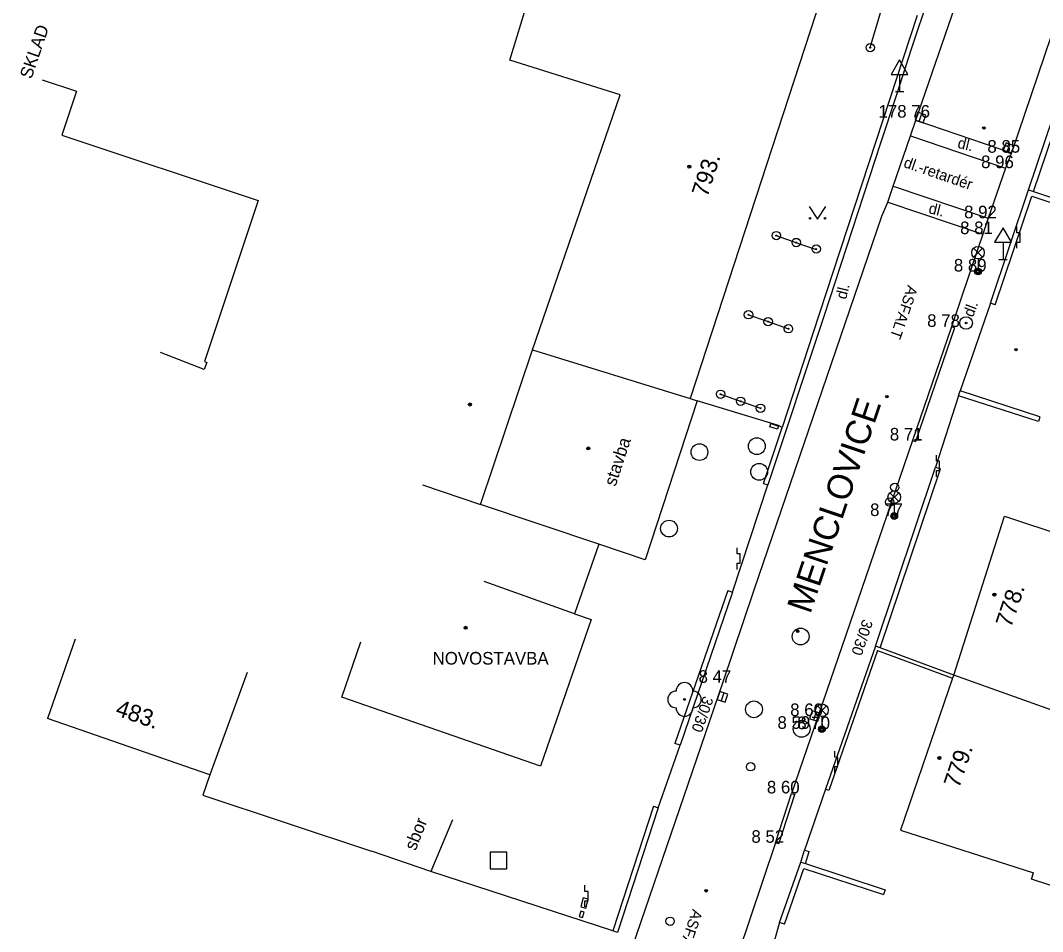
# Model space of a CAD drawing. Extents: x -538441 to -536770, y -1181008 to -1179809.
# Drawn here: x -538153.7 to -538092.8, y -1180711.7 to -1180657.4 of the extents above; entities that cross this region are included whole.
import ezdxf

# ---------------------------------------------------------------- set-up
doc = ezdxf.new("R2010")
doc.units = 0
for name, color, linetype in [('Vrstva 10', 7, 'Continuous'), ('Vrstva 11', 7, 'Continuous'), ('Vrstva 20', 7, 'Continuous'), ('Vrstva 21', 7, 'Continuous'), ('Vrstva 22', 7, 'Continuous'), ('Vrstva 24', 7, 'Continuous'), ('Vrstva 25', 7, 'Continuous'), ('Vrstva 26', 7, 'Continuous'), ('Vrstva 27', 7, 'Continuous'), ('Vrstva 28', 7, 'Continuous'), ('Vrstva 33', 7, 'Continuous'), ('Vrstva 34', 7, 'Continuous'), ('Vrstva 36', 7, 'Continuous'), ('Vrstva 39', 7, 'Continuous'), ('Vrstva 4', 7, 'Continuous'), ('Vrstva 40', 7, 'Continuous'), ('Vrstva 41', 7, 'Continuous'), ('Vrstva 47', 7, 'Continuous'), ('Vrstva 49', 7, 'Continuous'), ('Vrstva 5', 7, 'Continuous'), ('Vrstva 7', 7, 'Continuous'), ('Vrstva 8', 7, 'Continuous')]:
    doc.layers.add(name, color=color, linetype=linetype)

msp = doc.modelspace()

# ---------------------------------------------------------------- linework, layer by layer
at = {"layer": 'Vrstva 10'}
for p, q in [((-538090.51, -1180652.96), (-538094.67, -1180665.24)), ((-538100.376, -1180663.311), (-538097.28, -1180654.29)), ((-538103.09, -1180658.98), (-538102.38, -1180656.57)), ((-538094.67, -1180665.24), (-538095.03, -1180666.16)), ((-538095.03, -1180666.16), (-538096.06, -1180669.15)), ((-538096.67, -1180670.9), (-538098.26, -1180675.62)), ((-538098.26, -1180675.62), (-538100.58, -1180682.39)), ((-538108.73, -1180706.36), (-538107.78, -1180703.42)), ((-538108.73, -1180706.36), (-538112.31, -1180716.94))]:
    msp.add_line(p, q, dxfattribs=at)
for points in [[(-538102.4, -1180669.03), (-538102.046, -1180668.178), (-538101.723, -1180667.235), (-538100.696, -1180664.244), (-538100.376, -1180663.311)], [(-538111.88, -1180696.83), (-538110, -1180691.28), (-538102.4, -1180669.03)], [(-538096.06, -1180669.15), (-538096.39, -1180670.09), (-538096.67, -1180670.9)], [(-538108.688, -1180670.176), (-538107.529, -1180670.593), (-538106.31, -1180671.01)], [(-538110.344, -1180674.894), (-538109.174, -1180675.307), (-538107.966, -1180675.728)], [(-538112.008, -1180679.636), (-538110.819, -1180680.053), (-538109.63, -1180680.47)], [(-538100.58, -1180682.39), (-538103.86, -1180691.97), (-538107.78, -1180703.42)], [(-538126.17, -1180738.76), (-538120.85, -1180723.06), (-538111.88, -1180696.83)]]:
    msp.add_lwpolyline(points, dxfattribs=at)
at = {"layer": 'Vrstva 11'}
for p, q in [((-538100.376, -1180663.311), (-538094.67, -1180665.24)), ((-538100.696, -1180664.244), (-538095.03, -1180666.16)), ((-538101.723, -1180667.235), (-538096.06, -1180669.15)), ((-538102.046, -1180668.178), (-538096.39, -1180670.09)), ((-538098.07, -1180675.684), (-538100.39, -1180682.454)), ((-538098.07, -1180675.684), (-538098.26, -1180675.62)), ((-538100.58, -1180682.39), (-538100.39, -1180682.454)), ((-538108.539, -1180706.421), (-538107.589, -1180703.481)), ((-538107.78, -1180703.42), (-538107.589, -1180703.481)), ((-538108.539, -1180706.421), (-538108.73, -1180706.36))]:
    msp.add_line(p, q, dxfattribs=at)
at = {"layer": 'Vrstva 20'}
for centre, radius in [((-538096.32, -1180663.77), 0.075), ((-538096.32, -1180663.77), 0.0204), ((-538094.41, -1180676.98), 0.075), ((-538094.41, -1180676.98), 0.0204), ((-538102.1, -1180679.78), 0.075), ((-538102.1, -1180679.78), 0.0204), ((-538107.42, -1180693.748), 0.075), ((-538107.42, -1180693.748), 0.0204), ((-538112.87, -1180709.22), 0.075), ((-538112.87, -1180709.22), 0.0204)]:
    msp.add_circle(centre, radius, dxfattribs=at)
at = {"layer": 'Vrstva 21'}
for radius in [0.375, 0.05]:
    msp.add_circle((-538097.38, -1180675.39), radius, dxfattribs=at)
at = {"layer": 'Vrstva 22'}
msp.add_circle((-538114.16, -1180697.82), 0.05, dxfattribs=at)
for centre, start, end in [((-538114.16, -1180697.32), 0, 180), ((-538114.66, -1180697.82), 90, 270), ((-538113.66, -1180697.82), 270, 90), ((-538114.16, -1180698.32), 180, 0)]:
    msp.add_arc(centre, 0.5, start, end, dxfattribs=at)
at = {"layer": 'Vrstva 24'}
for p, q in [((-538094.349, -1180670.009), (-538094.35, -1180669.641)), ((-538094.166, -1180670.01), (-538094.349, -1180670.009)), ((-538094.166, -1180670.562), (-538094.166, -1180670.01)), ((-538094.35, -1180670.93), (-538094.349, -1180670.562)), ((-538094.349, -1180670.562), (-538094.166, -1180670.562)), ((-538099.139, -1180683.629), (-538099.14, -1180683.261)), ((-538098.956, -1180683.63), (-538099.139, -1180683.629)), ((-538098.956, -1180684.182), (-538098.956, -1180683.63)), ((-538099.14, -1180684.55), (-538099.139, -1180684.182)), ((-538099.139, -1180684.182), (-538098.956, -1180684.182)), ((-538111.019, -1180689.149), (-538111.02, -1180688.781)), ((-538110.836, -1180689.15), (-538111.019, -1180689.149)), ((-538110.836, -1180689.702), (-538110.836, -1180689.15)), ((-538111.02, -1180690.07), (-538111.019, -1180689.702)), ((-538111.019, -1180689.702), (-538110.836, -1180689.702)), ((-538105.209, -1180701.269), (-538105.21, -1180700.901)), ((-538105.026, -1180701.27), (-538105.209, -1180701.269)), ((-538105.026, -1180701.822), (-538105.026, -1180701.27)), ((-538105.21, -1180702.19), (-538105.209, -1180701.822)), ((-538105.209, -1180701.822), (-538105.026, -1180701.822)), ((-538120.09, -1180709.259), (-538120.09, -1180708.891)), ((-538119.907, -1180709.261), (-538120.09, -1180709.259)), ((-538119.907, -1180709.813), (-538119.907, -1180709.261)), ((-538120.09, -1180710.18), (-538120.09, -1180709.813)), ((-538120.09, -1180709.813), (-538119.907, -1180709.813))]:
    msp.add_line(p, q, dxfattribs=at)
for points in [[(-538109.07, -1180681.57), (-538109.007, -1180681.38), (-538108.561, -1180681.527), (-538108.623, -1180681.717), (-538109.07, -1180681.57)], [(-538120.19, -1180709.651), (-538120.33, -1180710.181), (-538120.03, -1180710.26), (-538119.89, -1180709.73), (-538120.19, -1180709.651)], [(-538120.425, -1180710.759), (-538120.23, -1180710.82), (-538120.13, -1180710.5), (-538120.332, -1180710.437), (-538120.425, -1180710.759)]]:
    msp.add_lwpolyline(points, dxfattribs=at)
at = {"layer": 'Vrstva 25'}
for centre, radius in [((-538103.09, -1180658.98), 0.25), ((-538103.09, -1180658.98), 0.0303), ((-538108.688, -1180670.176), 0.25), ((-538108.688, -1180670.176), 0.0303), ((-538107.499, -1180670.593), 0.25), ((-538107.499, -1180670.593), 0.0303), ((-538106.31, -1180670.98), 0.25), ((-538106.31, -1180670.98), 0.0303), ((-538110.344, -1180674.894), 0.25), ((-538110.344, -1180674.894), 0.0303), ((-538109.174, -1180675.307), 0.25), ((-538109.174, -1180675.307), 0.0303), ((-538107.966, -1180675.728), 0.25), ((-538107.966, -1180675.728), 0.0303), ((-538112.008, -1180679.636), 0.25), ((-538112.008, -1180679.636), 0.0303), ((-538110.819, -1180680.053), 0.25), ((-538110.819, -1180680.053), 0.0303), ((-538109.63, -1180680.47), 0.25), ((-538109.63, -1180680.47), 0.0303)]:
    msp.add_circle(centre, radius, dxfattribs=at)
at = {"layer": 'Vrstva 26'}
msp.add_lwpolyline([(-538125.739, -1180707.919), (-538124.741, -1180707.919), (-538124.741, -1180706.919), (-538125.739, -1180706.919)], close=True, dxfattribs=at)
at = {"layer": 'Vrstva 27'}
for p, q in [((-538100.183, -1180663.386), (-538100.017, -1180662.914)), ((-538094.945, -1180665.201), (-538094.755, -1180664.739)), ((-538111.819, -1180697.433), (-538111.981, -1180697.907)), ((-538106.461, -1180699.05), (-538106.319, -1180698.57))]:
    msp.add_line(p, q, dxfattribs=at)
for points in [[(-538099.947, -1180663.469), (-538099.781, -1180662.997), (-538100.253, -1180662.831), (-538100.419, -1180663.303)], [(-538094.714, -1180665.297), (-538094.523, -1180664.834), (-538094.986, -1180664.643), (-538095.177, -1180665.106)], [(-538112.056, -1180697.353), (-538112.217, -1180697.826), (-538111.744, -1180697.987), (-538111.583, -1180697.514)], [(-538106.222, -1180699.121), (-538106.079, -1180698.642), (-538106.558, -1180698.499), (-538106.701, -1180698.978)]]:
    msp.add_lwpolyline(points, close=True, dxfattribs=at)
for centre in [(-538113.27, -1180683.08), (-538109.85, -1180682.73), (-538109.71, -1180684.26), (-538115.08, -1180687.64), (-538107.24, -1180694.07), (-538110.02, -1180698.41), (-538107.18, -1180699.57)]:
    msp.add_circle(centre, 0.5, dxfattribs=at)
at = {"layer": 'Vrstva 28'}
for centre in [(-538101.63, -1180685.18), (-538101.94, -1180686.06), (-538110.22, -1180701.83), (-538115.02, -1180711.04)]:
    msp.add_circle(centre, 0.25, dxfattribs=at)
at = {"layer": 'Vrstva 33'}
for p, q in [((-538096.935, -1180671.46), (-538096.405, -1180670.93)), ((-538096.935, -1180670.93), (-538096.405, -1180671.46)), ((-538096.67, -1180671.57), (-538096.67, -1180672.32)), ((-538101.925, -1180686.03), (-538101.395, -1180685.5)), ((-538101.925, -1180685.5), (-538101.395, -1180686.03)), ((-538101.66, -1180686.14), (-538101.66, -1180686.89)), ((-538106.235, -1180698.73), (-538105.705, -1180698.2)), ((-538106.235, -1180698.2), (-538105.705, -1180698.73)), ((-538105.97, -1180698.84), (-538105.97, -1180699.59))]:
    msp.add_line(p, q, dxfattribs=at)
for centre, radius in [((-538096.67, -1180671.195), 0.375), ((-538096.67, -1180672.32), 0.2), ((-538096.67, -1180672.32), 0.145), ((-538096.67, -1180672.32), 0.0876), ((-538101.66, -1180685.765), 0.375), ((-538101.66, -1180686.89), 0.2), ((-538101.66, -1180686.89), 0.145), ((-538101.66, -1180686.89), 0.0876), ((-538105.97, -1180698.465), 0.375), ((-538105.97, -1180699.59), 0.2), ((-538105.97, -1180699.59), 0.145), ((-538105.97, -1180699.59), 0.0876)]:
    msp.add_circle(centre, radius, dxfattribs=at)
at = {"layer": 'Vrstva 34'}
for p, q in [((-538101.345, -1180660.576), (-538101.345, -1180661.594)), ((-538101.595, -1180661.594), (-538101.095, -1180661.594)), ((-538095.18, -1180670.58), (-538095.18, -1180671.598)), ((-538095.43, -1180671.598), (-538094.93, -1180671.598))]:
    msp.add_line(p, q, dxfattribs=at)
for points in [[(-538101.845, -1180660.576), (-538100.845, -1180660.576), (-538101.345, -1180659.71)], [(-538095.68, -1180670.58), (-538094.68, -1180670.58), (-538095.18, -1180669.714)]]:
    msp.add_lwpolyline(points, close=True, dxfattribs=at)
at = {"layer": 'Vrstva 36'}
msp.add_lwpolyline([(-538106.734, -1180668.448), (-538106.234, -1180669.198), (-538105.734, -1180668.448)], dxfattribs=at)
for centre in [(-538106.684, -1180669.148), (-538105.785, -1180669.148)]:
    msp.add_circle(centre, 0.05, dxfattribs=at)
at = {"layer": 'Vrstva 39'}
for centre, radius in [((-538113.871, -1180666.069), 0.09), ((-538113.871, -1180666.069), 0.0398), ((-538126.942, -1180680.244), 0.09), ((-538126.942, -1180680.244), 0.0398), ((-538119.889, -1180682.864), 0.09), ((-538119.889, -1180682.864), 0.0398), ((-538095.698, -1180691.573), 0.09), ((-538095.698, -1180691.573), 0.0398), ((-538127.204, -1180693.548), 0.09), ((-538127.204, -1180693.548), 0.0398), ((-538098.973, -1180701.309), 0.09), ((-538098.973, -1180701.309), 0.0398)]:
    msp.add_circle(centre, radius, dxfattribs=at)
at = {"layer": 'Vrstva 5'}
for p, q in [((-538105.78, -1180655.28), (-538113.83, -1180679.89)), ((-538117.99, -1180661.8), (-538124.57, -1180659.73)), ((-538152.431, -1180660.9), (-538150.39, -1180661.58)), ((-538150.39, -1180661.58), (-538151.26, -1180664.19)), ((-538123.21, -1180676.99), (-538117.99, -1180661.8)), ((-538151.26, -1180664.19), (-538139.554, -1180668.092)), ((-538139.554, -1180668.092), (-538142.75, -1180677.68)), ((-538126.31, -1180686.2), (-538123.21, -1180676.99)), ((-538123.21, -1180676.99), (-538113.83, -1180679.89)), ((-538142.78, -1180678.15), (-538145.368, -1180677.14)), ((-538142.75, -1180677.68), (-538142.62, -1180677.74)), ((-538142.62, -1180677.74), (-538142.78, -1180678.15)), ((-538113.402, -1180680.03), (-538116.5, -1180689.5)), ((-538113.83, -1180679.89), (-538113.402, -1180680.03)), ((-538129.762, -1180685.038), (-538126.31, -1180686.2)), ((-538098.12, -1180696.37), (-538095.09, -1180686.89)), ((-538095.09, -1180686.89), (-538087.19, -1180689.55)), ((-538119.267, -1180688.569), (-538120.706, -1180692.719)), ((-538120.706, -1180692.719), (-538126.103, -1180690.798)), ((-538120.706, -1180692.719), (-538119.72, -1180693.06)), ((-538119.72, -1180693.06), (-538122.74, -1180701.79)), ((-538150.47, -1180694.226), (-538152.11, -1180698.95)), ((-538134.58, -1180697.68), (-538133.436, -1180694.385)), ((-538140.21, -1180696.21), (-538142.43, -1180702.31)), ((-538090.48, -1180699.11), (-538098.12, -1180696.37)), ((-538122.74, -1180701.79), (-538134.58, -1180697.68)), ((-538142.43, -1180702.31), (-538152.11, -1180698.95)), ((-538127.98, -1180704.99), (-538129.27, -1180708.07)), ((-538101.28, -1180705.6), (-538093.36, -1180708.16)), ((-538129.27, -1180708.07), (-538132.81, -1180706.86)), ((-538093.48, -1180708.52), (-538093.36, -1180708.16)), ((-538091.48, -1180709.18), (-538093.48, -1180708.52))]:
    msp.add_line(p, q, dxfattribs=at)
for points in [[(-538124.57, -1180659.73), (-538123.683, -1180656.862), (-538121.816, -1180650.822)], [(-538116.5, -1180689.5), (-538119.267, -1180688.569), (-538126.31, -1180686.2)], [(-538098.12, -1180696.37), (-538098.185, -1180696.559), (-538101.28, -1180705.6)]]:
    msp.add_lwpolyline(points, dxfattribs=at)
at = {"layer": 'Vrstva 7'}
for p, q in [((-538098.766, -1180653.367), (-538100.625, -1180659.018)), ((-538100.302, -1180657.074), (-538102.765, -1180664.577)), ((-538093.375, -1180667.554), (-538090.52, -1180659.12)), ((-538102.765, -1180664.577), (-538106.145, -1180674.917)), ((-538102.48, -1180664.67), (-538105.86, -1180675.01)), ((-538095.646, -1180674.296), (-538093.471, -1180667.839)), ((-538093.471, -1180667.839), (-538088.913, -1180669.352)), ((-538105.86, -1180675.01), (-538109.19, -1180685.04)), ((-538106.145, -1180674.917), (-538108.333, -1180681.611)), ((-538092.98, -1180680.971), (-538097.74, -1180679.44)), ((-538102.498, -1180694.745), (-538098.915, -1180684.075)), ((-538109.443, -1180684.956), (-538109.19, -1180685.04)), ((-538111.584, -1180691.331), (-538114.742, -1180700.439)), ((-538102.78, -1180694.64), (-538105.75, -1180703.17)), ((-538102.658, -1180694.899), (-538098.185, -1180696.559)), ((-538142.43, -1180702.31), (-538142.85, -1180703.52)), ((-538142.85, -1180703.52), (-538132.81, -1180706.86)), ((-538116.015, -1180704.177), (-538118.435, -1180711.617)), ((-538106.944, -1180707.604), (-538106.723, -1180706.889)), ((-538118.435, -1180711.617), (-538129.27, -1180708.07))]:
    msp.add_line(p, q, dxfattribs=at)
for points in [[(-538093.66, -1180667.46), (-538090.71, -1180658.7), (-538090.426, -1180658.796)], [(-538100.625, -1180659.018), (-538101.554, -1180661.844), (-538102.48, -1180664.67)], [(-538095.646, -1180674.296), (-538095.93, -1180674.2), (-538093.66, -1180667.46)], [(-538093.66, -1180667.46), (-538093.375, -1180667.554), (-538088.81, -1180669.07)], [(-538092.98, -1180680.971), (-538093.071, -1180681.256), (-538097.831, -1180679.725), (-538097.74, -1180679.44)], [(-538108.56, -1180681.49), (-538113.402, -1180680.03)], [(-538109.443, -1180684.956), (-538108.333, -1180681.611), (-538108.56, -1180681.49)], [(-538102.78, -1180694.64), (-538099.2, -1180683.98), (-538098.915, -1180684.075)], [(-538111.584, -1180691.331), (-538111.3, -1180691.43), (-538114.42, -1180700.55)], [(-538098.12, -1180696.37), (-538102.498, -1180694.745), (-538102.78, -1180694.64)], [(-538102.658, -1180694.899), (-538105.561, -1180703.236), (-538105.75, -1180703.17)], [(-538114.42, -1180700.55), (-538114.742, -1180700.439)], [(-538116.015, -1180704.177), (-538115.73, -1180704.27), (-538118.15, -1180711.71), (-538118.435, -1180711.617)], [(-538107.23, -1180707.51), (-538107.01, -1180706.8), (-538106.723, -1180706.889)], [(-538108.207, -1180711.209), (-538108.49, -1180711.11), (-538107.23, -1180707.51)], [(-538107.23, -1180707.51), (-538106.944, -1180707.604), (-538102.2, -1180709.16), (-538102.294, -1180709.445)], [(-538108.207, -1180711.209), (-538107.044, -1180707.887), (-538102.294, -1180709.445)]]:
    msp.add_lwpolyline(points, dxfattribs=at)
at = {"layer": 'Vrstva 8'}
for p, q in [((-538095.93, -1180674.2), (-538097.74, -1180679.44)), ((-538097.831, -1180679.725), (-538099.2, -1180683.98)), ((-538111.3, -1180691.43), (-538109.19, -1180685.04)), ((-538115.73, -1180704.27), (-538114.42, -1180700.55)), ((-538105.75, -1180703.17), (-538107.01, -1180706.8)), ((-538108.49, -1180711.11), (-538108.79, -1180712.16))]:
    msp.add_line(p, q, dxfattribs=at)

# ---------------------------------------------------------------- texts
at = {"layer": 'Vrstva 4'}
for s, p in [('178 76 ', (-538102.6, -1180663.15)), (' 8 85', (-538096.39, -1180665.24)), (' 8 96', (-538096.766, -1180666.16)), (' 8 92', (-538097.779, -1180669.15)), (' 8 81', (-538098.015, -1180670.09)), (' 8 89', (-538098.389, -1180672.32)), (' 8 78', (-538099.979, -1180675.62)), (' 8 71', (-538102.205, -1180682.39)), (' 8 77', (-538103.379, -1180686.89)), (' 8 47', (-538113.599, -1180696.83)), (' 8 60', (-538108.139, -1180698.81)), (' 8 59', (-538108.899, -1180699.57)), (' 8 70', (-538107.719, -1180699.59)), (' 8 60', (-538109.529, -1180703.42)), (' 8 52', (-538110.449, -1180706.36))]:
    msp.add_text(s, height=0.75, dxfattribs=at).set_placement(p)
at = {"layer": 'Vrstva 40'}
for s, rotation, p in [('dl.', 346.25013, (-538097.932, -1180664.944)), ('dl.-retardér', 341.03671, (-538101.152, -1180666.085)), ('dl.', 346.25013, (-538099.658, -1180668.838)), ('dl.', 76.25012, (-538104.529, -1180674.012)), ('ASFALT', 251.00783, (-538100.857, -1180673.095)), ('dl.', 69.34359, (-538096.972, -1180675.082)), ('30/30', 251.40399, (-538103.534, -1180692.994)), ('30/30', 250.6392, (-538113.029, -1180697.579)), ('ASFALT', 250.63351, (-538113.673, -1180710.276))]:
    msp.add_text(s, height=0.65, rotation=rotation, dxfattribs=at).set_placement(p)
at = {"layer": 'Vrstva 41'}
for s, rotation, p in [('SKLAD', 71.25046, (-538153.07, -1180660.892)), ('stavba', 71.88509, (-538118.266, -1180685.165)), ('sbor', 68.28176, (-538130.184, -1180706.872))]:
    msp.add_text(s, height=0.75, rotation=rotation, dxfattribs=at).set_placement(p)
msp.add_text('NOVOSTAVBA', height=0.75, dxfattribs=at).set_placement((-538129.164, -1180695.741))
at = {"layer": 'Vrstva 47'}
for s, rotation, p in [('793.', 71.88693, (-538112.805, -1180667.935)), ('778.', 71.09924, (-538094.708, -1180693.592)), ('483.', 340.85773, (-538148.124, -1180698.746)), ('779.', 71.10075, (-538097.802, -1180703.154))]:
    msp.add_text(s, height=1, rotation=rotation, dxfattribs=at).set_placement(p)
at = {"layer": 'Vrstva 49'}
msp.add_text('MENCLOVICE', height=1.5, rotation=71.35841, dxfattribs=at).set_placement((-538106.664, -1180692.773))

doc.saveas('drawing.dxf')
